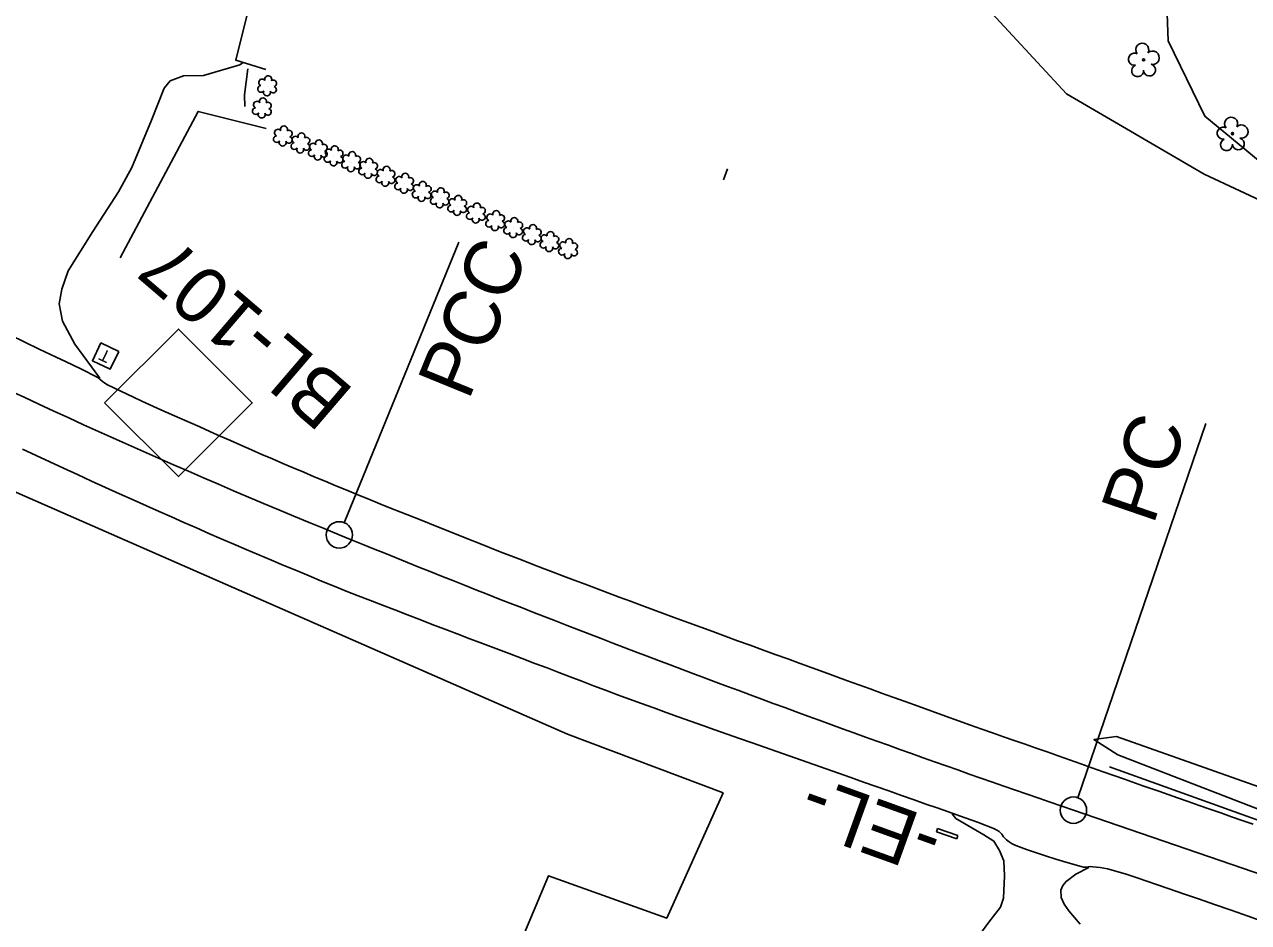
# Model space of a CAD drawing. Extents: x 478596 to 483012, y 490885 to 495165.
# Drawn here: x 479587.5 to 479935.6, y 493466.1 to 493721.5 of the extents above; entities that cross this region are included whole.
import ezdxf

# ---------------------------------------------------------------- set-up
doc = ezdxf.new("R2010")
doc.units = 0
for name, color, linetype in [('CTL Secondary Horizontal and Vertical CELL', 7, 'Continuous'), ('CTL Secondary Horizontal and Vertical Text', 7, 'Continuous'), ('Exist Guardrail', 7, 'Continuous'), ('Exist Horizontal Alignment', 7, 'Continuous'), ('Exist Horizontal Alignment Direction Label', 7, 'Continuous'), ('Exist Other Culture Area Outline', 7, 'Continuous'), ('Exist Other Culture Fence Line', 7, 'Continuous'), ('Exist Roads EOP', 7, 'Continuous'), ('Exist Roads Soil', 7, 'Continuous'), ('Exist Structure Minor Head and End Wall', 7, 'Continuous'), ('Exist Utilities Telephone Pedestal CELL', 7, 'Continuous'), ('Exist Vegetation Hedge Row', 7, 'Continuous'), ('Exist Vegetation Shrub CELL', 7, 'Continuous'), ('Exist Vegetation Tree CELL', 7, 'Continuous'), ('Exist Vegetation Woods Line', 7, 'Continuous')]:
    doc.layers.add(name, color=color, linetype=linetype)

msp = doc.modelspace()

# ---------------------------------------------------------------- linework, layer by layer
at = {"layer": 'CTL Secondary Horizontal and Vertical CELL'}
msp.add_line((479631.14, 493613.86), (479631.14, 493613.86), dxfattribs=at)
msp.add_lwpolyline([(479610.28, 493613.93), (479631.25, 493634.89), (479652.25, 493613.89), (479631.28, 493592.93)], close=True, dxfattribs=at)
at = {"layer": 'Exist Guardrail'}
msp.add_line((479896.1, 493510.36), (479982.05, 493479.53), dxfattribs=at)
at = {"layer": 'Exist Horizontal Alignment'}
for p, q in [((479678.44, 493579.83), (479710.98, 493659.56)), ((479887.04, 493501.61), (479923.5, 493608.01)), ((480512.88, 493283.24), (479885.83, 493498.07))]:
    msp.add_line(p, q, dxfattribs=at)
for centre in [(479677.03, 493576.36), (479885.83, 493498.07)]:
    msp.add_circle(centre, 3.75, dxfattribs=at)
for centre, radius, start, end in [((480448.9, 495467.9), 2042.96, 239.44048, 247.8014), ((481145.82, 497175.77), 3887.55, 247.8014, 251.08844)]:
    msp.add_arc(centre, radius, start, end, dxfattribs=at)
at = {"layer": 'Exist Other Culture Area Outline'}
for points in [[(479656.14, 493708.66), (479647.59, 493711.33), (479650.8, 493724.32), (479649.1, 493735.54)], [(479651.05, 493708.93), (479650.1, 493701.48), (479650.19, 493698.21)], [(479787.48, 493680.47), (479786.33, 493677.33)]]:
    msp.add_lwpolyline(points, dxfattribs=at)
at = {"layer": 'Exist Other Culture Fence Line'}
msp.add_lwpolyline([(479614.74, 493655.17), (479636.92, 493696.8), (479656.2, 493691.97)], dxfattribs=at)
at = {"layer": 'Exist Roads EOP'}
for points in [[(479936.94, 493494.07), (479933.81, 493495.16), (479930.76, 493496.22), (479927.73, 493497.28), (479924.66, 493498.35), (479921.57, 493499.43), (479918.43, 493500.53), (479915.41, 493501.59), (479910.12, 493503.44), (479905.6, 493505.03), (479900.35, 493506.87), (479897.36, 493507.92), (479894.24, 493509.02), (479891.09, 493510.13), (479887.91, 493511.25), (479884.71, 493512.38), (479881.5, 493513.51), (479878.33, 493514.63), (479875.19, 493515.73), (479872.09, 493516.81), (479869, 493517.89), (479865.91, 493518.97), (479862.83, 493520.05), (479859.74, 493521.13), (479856.53, 493522.26), (479853.1, 493523.48), (479849.45, 493524.79), (479845.56, 493526.2), (479841.66, 493527.61), (479837.97, 493528.94), (479834.49, 493530.2), (479831.2, 493531.39), (479828.01, 493532.54), (479824.79, 493533.71), (479821.55, 493534.9), (479818.27, 493536.1), (479814.95, 493537.32), (479811.56, 493538.56), (479808.09, 493539.82), (479804.55, 493541.1), (479800.98, 493542.39), (479797.42, 493543.68), (479793.86, 493544.98), (479790.32, 493546.27), (479786.79, 493547.56), (479783.3, 493548.84), (479779.84, 493550.1), (479776.41, 493551.35), (479773.02, 493552.59), (479769.67, 493553.82), (479766.36, 493555.04), (479763.1, 493556.26), (479759.85, 493557.47), (479756.62, 493558.68), (479753.38, 493559.9), (479750.15, 493561.11), (479746.96, 493562.32), (479743.84, 493563.5), (479740.79, 493564.66), (479737.81, 493565.79), (479734.85, 493566.92), (479731.88, 493568.06), (479728.87, 493569.22), (479725.85, 493570.4), (479722.81, 493571.58), (479719.78, 493572.78), (479716.75, 493573.97), (479713.73, 493575.18), (479710.77, 493576.36), (479705.24, 493578.56), (479700.1, 493580.6), (479694.56, 493582.81), (479691.59, 493584), (479688.54, 493585.23), (479685.45, 493586.47), (479682.34, 493587.74), (479679.2, 493589.03), (479676.06, 493590.32), (479672.97, 493591.61), (479669.92, 493592.88), (479666.92, 493594.15), (479663.94, 493595.42), (479660.96, 493596.69), (479657.99, 493597.98), (479655.01, 493599.26), (479652.04, 493600.56), (479649.07, 493601.86), (479646.11, 493603.16), (479643.14, 493604.47), (479640.21, 493605.77), (479637.33, 493607.05), (479634.5, 493608.3), (479631.72, 493609.52), (479626.27, 493611.96), (479620.9, 493614.43), (479618.46, 493615.57), (479614.9, 493617.24), (479610.91, 493619.17), (479610.25, 493619.56), (479609.69, 493619.98), (479608.92, 493620.67), (479608.34, 493621.09), (479603.52, 493623.59), (479599.19, 493625.65), (479596.54, 493626.87), (479591.69, 493629.16), (479587.74, 493631.08), (479583.11, 493633.38)], [(479940.28, 493466.24), (479935.53, 493467.9), (479930.68, 493469.59), (479925.9, 493471.25), (479921.38, 493472.83), (479917.11, 493474.32), (479913.09, 493475.72), (479909.49, 493476.97), (479903.98, 493478.85), (479900.52, 493479.97), (479895.53, 493481.4), (479893.39, 493481.8), (479891.39, 493482), (479890.65, 493482.02), (479890.1, 493481.98), (479889.74, 493481.88), (479889.34, 493481.83), (479888.66, 493481.9), (479883.68, 493483.25), (479880.79, 493484.16), (479877.88, 493485.12), (479872.52, 493486.93), (479869.49, 493488.05), (479868.43, 493488.54), (479867.55, 493489.06), (479866.79, 493489.64), (479866.18, 493490.23), (479865.95, 493490.52), (479865.43, 493491.28), (479865.25, 493491.48), (479865.08, 493491.65), (479864.66, 493491.98), (479864.08, 493492.36), (479863.33, 493492.77), (479858.54, 493494.68), (479855.01, 493495.94), (479850.02, 493497.69), (479847.06, 493498.72), (479843.89, 493499.82), (479840.53, 493501.01), (479836.96, 493502.26), (479833.31, 493503.55), (479829.69, 493504.82), (479826.1, 493506.08), (479822.56, 493507.32), (479819.03, 493508.55), (479815.51, 493509.79), (479811.99, 493511.03), (479808.49, 493512.27), (479804.98, 493513.51), (479801.47, 493514.75), (479797.95, 493515.98), (479794.42, 493517.21), (479790.89, 493518.44), (479787.37, 493519.67), (479783.87, 493520.91), (479780.39, 493522.16), (479776.91, 493523.4), (479773.43, 493524.65), (479769.95, 493525.89), (479766.47, 493527.14), (479763, 493528.38), (479759.55, 493529.64), (479756.12, 493530.91), (479752.71, 493532.18), (479749.33, 493533.46), (479745.99, 493534.72), (479742.7, 493535.98), (479739.44, 493537.23), (479736.13, 493538.51), (479732.67, 493539.83), (479729.06, 493541.19), (479725.31, 493542.61), (479721.52, 493544.04), (479717.8, 493545.45), (479714.15, 493546.84), (479710.57, 493548.21), (479707.03, 493549.56), (479703.48, 493550.92), (479699.93, 493552.29), (479696.38, 493553.65), (479692.84, 493555.02), (479689.34, 493556.37), (479685.87, 493557.72), (479682.44, 493559.05), (479679.01, 493560.4), (479675.53, 493561.79), (479672.01, 493563.23), (479668.45, 493564.7), (479664.87, 493566.2), (479661.29, 493567.7), (479657.71, 493569.2), (479654.14, 493570.71), (479650.57, 493572.22), (479647.02, 493573.74), (479643.47, 493575.27), (479639.94, 493576.8), (479636.4, 493578.35), (479632.86, 493579.89), (479629.31, 493581.45), (479625.76, 493583.01), (479622.15, 493584.61), (479618.41, 493586.28), (479614.55, 493588.02), (479610.58, 493589.82), (479606.56, 493591.66), (479602.57, 493593.49), (479598.62, 493595.32), (479594.7, 493597.14), (479590.8, 493598.96), (479586.93, 493600.76)]]:
    msp.add_lwpolyline(points, dxfattribs=at)
at = {"layer": 'Exist Roads Soil'}
for points in [[(479649.67, 493710.68), (479648.77, 493710.08), (479638.4, 493706.97), (479632.75, 493706.94), (479628.96, 493705.46), (479627.23, 493703.37), (479623.57, 493694.34), (479618.02, 493680.83), (479614.21, 493673.87), (479606.95, 493662.62), (479599.93, 493651.49), (479598.16, 493646.26), (479597.33, 493642.02), (479598.35, 493637.13), (479601.78, 493630.63), (479608.95, 493620.95)], [(479851.32, 493497.04), (479852.36, 493495.74), (479860.32, 493491.06), (479863.2, 493489.26), (479864.77, 493486.6), (479866.05, 493483.62), (479866.18, 493479.43), (479865.93, 493473.04), (479865.12, 493470.45), (479861.76, 493466.26), (479858.89, 493462.36)], [(479890.25, 493481.73), (479886.49, 493479.86), (479883.73, 493477.8), (479882.82, 493476.68), (479882.28, 493475.33), (479882.36, 493473.27), (479883.21, 493471.33), (479884.47, 493469.43), (479887.77, 493465.65)]]:
    msp.add_lwpolyline(points, dxfattribs=at)
at = {"layer": 'Exist Structure Minor Head and End Wall'}
for p, q in [((479846.84, 493491.93), (479847.17, 493492.88)), ((479847.17, 493492.88), (479852.97, 493490.86)), ((479846.84, 493491.93), (479852.64, 493489.92)), ((479852.64, 493489.92), (479852.97, 493490.86))]:
    msp.add_line(p, q, dxfattribs=at)
at = {"layer": 'Exist Utilities Telephone Pedestal CELL'}
msp.add_line((479610.6, 493627.16), (479610.6, 493627.16), dxfattribs=at)
msp.add_lwpolyline([(479614.28, 493628.54), (479609.23, 493630.95), (479606.82, 493625.9), (479611.87, 493623.49), (479614.28, 493628.54)], dxfattribs=at)
at = {"layer": 'Exist Vegetation Hedge Row'}
for points in [[(479912.31, 493729.75), (479912.77, 493716.89), (479923.17, 493695.39), (479948.15, 493674.84), (479943.28, 493669.47), (479923.02, 493678.95), (479883.84, 493701.77), (479859.15, 493728.66)], [(479982.85, 493482.21), (479949.94, 493493.89), (479898.42, 493513.77), (479891.65, 493518.15), (479898.04, 493519.04), (479985.49, 493488.15)]]:
    msp.add_lwpolyline(points, dxfattribs=at)
at = {"layer": 'Exist Vegetation Shrub CELL'}
for p, q in [((479656.58, 493703.89), (479656.58, 493703.89)), ((479655.09, 493697.58), (479655.09, 493697.58)), ((479661.06, 493689.62), (479661.06, 493689.62)), ((479666.04, 493687.62), (479666.04, 493687.62)), ((479671.01, 493685.63), (479671.01, 493685.63)), ((479675.49, 493683.97), (479675.49, 493683.97)), ((479680.47, 493682.32), (479680.47, 493682.32)), ((479685.33, 493680.43), (479685.33, 493680.43)), ((479690.25, 493678.17), (479690.25, 493678.17)), ((479695.56, 493676.18), (479695.56, 493676.18)), ((479700.54, 493673.85), (479700.54, 493673.85)), ((479705.68, 493672.03), (479705.68, 493672.03)), ((479710.65, 493669.87), (479710.65, 493669.87)), ((479715.96, 493667.71), (479715.96, 493667.71)), ((479721.43, 493665.56), (479721.43, 493665.56)), ((479726.57, 493663.57), (479726.57, 493663.57)), ((479731.88, 493661.57), (479731.88, 493661.57)), ((479736.86, 493659.58), (479736.86, 493659.58)), ((479742.16, 493657.59), (479742.16, 493657.59))]:
    msp.add_line(p, q, dxfattribs=at)
for centre, radius, start, end in [((479655.1, 493705.01), 0.968, 35.8908, 245.4216), ((479656.81, 493705.93), 0.99, 334.8391, 200.4717), ((479658.26, 493704.75), 0.929, 284.4567, 126.0861), ((479654.78, 493703.18), 0.955, 95.1099, 327.9534), ((479656.46, 493702.2), 0.984, 151.2797, 21.387), ((479658.22, 493702.96), 0.937, 204.9913, 73.4601), ((479653.61, 493698.71), 0.968, 35.8908, 245.4216), ((479655.32, 493699.62), 0.99, 334.8391, 200.4717), ((479656.76, 493698.45), 0.929, 284.4567, 126.0861), ((479653.29, 493696.88), 0.955, 95.1099, 327.9534), ((479654.96, 493695.9), 0.984, 151.2797, 21.387), ((479656.73, 493696.65), 0.937, 204.9913, 73.4601), ((479659.58, 493690.74), 0.968, 35.8908, 245.4216), ((479661.29, 493691.66), 0.99, 334.8391, 200.4717), ((479662.73, 493690.48), 0.929, 284.4567, 126.0861), ((479659.26, 493688.91), 0.955, 95.1099, 327.9534), ((479660.93, 493687.93), 0.984, 151.2797, 21.387), ((479662.7, 493688.69), 0.937, 204.9913, 73.4601), ((479664.24, 493686.92), 0.955, 95.1099, 327.9534), ((479664.56, 493688.75), 0.968, 35.8908, 245.4216), ((479666.27, 493689.67), 0.99, 334.8391, 200.4717), ((479667.71, 493688.49), 0.929, 284.4567, 126.0861), ((479671.24, 493687.67), 0.99, 334.8391, 200.4717), ((479665.91, 493685.94), 0.984, 151.2797, 21.387), ((479667.68, 493686.7), 0.937, 204.9913, 73.4601), ((479669.21, 493684.93), 0.955, 95.1099, 327.9534), ((479669.53, 493686.76), 0.968, 35.8908, 245.4216), ((479670.89, 493683.95), 0.984, 151.2797, 21.387), ((479672.65, 493684.7), 0.937, 204.9913, 73.4601), ((479672.69, 493686.5), 0.929, 284.4567, 126.0861), ((479674.01, 493685.1), 0.968, 35.8908, 245.4216), ((479675.72, 493686.01), 0.99, 334.8391, 200.4717), ((479677.16, 493684.84), 0.929, 284.4567, 126.0861), ((479678.98, 493683.44), 0.968, 35.8908, 245.4216), ((479680.7, 493684.36), 0.99, 334.8391, 200.4717), ((479673.69, 493683.27), 0.955, 95.1099, 327.9534), ((479675.36, 493682.29), 0.984, 151.2797, 21.387), ((479677.13, 493683.05), 0.937, 204.9913, 73.4601), ((479678.67, 493681.61), 0.955, 95.1099, 327.9534), ((479680.34, 493680.63), 0.984, 151.2797, 21.387), ((479682.1, 493681.39), 0.937, 204.9913, 73.4601), ((479682.14, 493683.18), 0.929, 284.4567, 126.0861), ((479683.85, 493681.56), 0.968, 35.8908, 245.4216), ((479685.56, 493682.47), 0.99, 334.8391, 200.4717), ((479687, 493681.3), 0.929, 284.4567, 126.0861), ((479690.48, 493680.21), 0.99, 334.8391, 200.4717), ((479683.53, 493679.73), 0.955, 95.1099, 327.9534), ((479685.2, 493678.75), 0.984, 151.2797, 21.387), ((479686.97, 493679.51), 0.937, 204.9913, 73.4601), ((479688.45, 493677.46), 0.955, 95.1099, 327.9534), ((479688.77, 493679.29), 0.968, 35.8908, 245.4216), ((479691.89, 493677.24), 0.937, 204.9913, 73.4601), ((479691.92, 493679.04), 0.929, 284.4567, 126.0861), ((479694.08, 493677.3), 0.968, 35.8908, 245.4216), ((479695.79, 493678.22), 0.99, 334.8391, 200.4717), ((479697.23, 493677.04), 0.929, 284.4567, 126.0861), ((479690.12, 493676.48), 0.984, 151.2797, 21.387), ((479693.76, 493675.47), 0.955, 95.1099, 327.9534), ((479695.43, 493674.49), 0.984, 151.2797, 21.387), ((479697.2, 493675.25), 0.937, 204.9913, 73.4601), ((479698.74, 493673.15), 0.955, 95.1099, 327.9534), ((479699.05, 493674.98), 0.968, 35.8908, 245.4216), ((479700.76, 493675.89), 0.99, 334.8391, 200.4717), ((479702.21, 493674.72), 0.929, 284.4567, 126.0861), ((479704.19, 493673.15), 0.968, 35.8908, 245.4216), ((479705.91, 493674.07), 0.99, 334.8391, 200.4717), ((479700.41, 493672.17), 0.984, 151.2797, 21.387), ((479702.17, 493672.92), 0.937, 204.9913, 73.4601), ((479703.88, 493671.32), 0.955, 95.1099, 327.9534), ((479705.55, 493670.34), 0.984, 151.2797, 21.387), ((479707.31, 493671.1), 0.937, 204.9913, 73.4601), ((479707.35, 493672.9), 0.929, 284.4567, 126.0861), ((479709.17, 493671), 0.968, 35.8908, 245.4216), ((479710.88, 493671.91), 0.99, 334.8391, 200.4717), ((479712.32, 493670.74), 0.929, 284.4567, 126.0861), ((479716.19, 493669.75), 0.99, 334.8391, 200.4717), ((479708.85, 493669.17), 0.955, 95.1099, 327.9534), ((479710.52, 493668.19), 0.984, 151.2797, 21.387), ((479712.29, 493668.94), 0.937, 204.9913, 73.4601), ((479714.16, 493667.01), 0.955, 95.1099, 327.9534), ((479714.48, 493668.84), 0.968, 35.8908, 245.4216), ((479717.6, 493666.78), 0.937, 204.9913, 73.4601), ((479717.63, 493668.58), 0.929, 284.4567, 126.0861), ((479719.95, 493666.68), 0.968, 35.8908, 245.4216), ((479721.66, 493667.6), 0.99, 334.8391, 200.4717), ((479723.1, 493666.43), 0.929, 284.4567, 126.0861), ((479715.83, 493666.03), 0.984, 151.2797, 21.387), ((479719.63, 493664.85), 0.955, 95.1099, 327.9534), ((479721.3, 493663.87), 0.984, 151.2797, 21.387), ((479723.07, 493664.63), 0.937, 204.9913, 73.4601), ((479724.77, 493662.86), 0.955, 95.1099, 327.9534), ((479725.09, 493664.69), 0.968, 35.8908, 245.4216), ((479726.8, 493665.61), 0.99, 334.8391, 200.4717), ((479728.21, 493662.64), 0.937, 204.9913, 73.4601), ((479728.25, 493664.43), 0.929, 284.4567, 126.0861), ((479730.4, 493662.7), 0.968, 35.8908, 245.4216), ((479732.11, 493663.61), 0.99, 334.8391, 200.4717), ((479726.45, 493661.88), 0.984, 151.2797, 21.387), ((479730.08, 493660.87), 0.955, 95.1099, 327.9534), ((479731.75, 493659.89), 0.984, 151.2797, 21.387), ((479733.52, 493660.65), 0.937, 204.9913, 73.4601), ((479733.55, 493662.44), 0.929, 284.4567, 126.0861), ((479735.37, 493660.71), 0.968, 35.8908, 245.4216), ((479737.09, 493661.62), 0.99, 334.8391, 200.4717), ((479738.53, 493660.45), 0.929, 284.4567, 126.0861), ((479742.39, 493659.63), 0.99, 334.8391, 200.4717), ((479735.06, 493658.88), 0.955, 95.1099, 327.9534), ((479736.73, 493657.9), 0.984, 151.2797, 21.387), ((479738.49, 493658.65), 0.937, 204.9913, 73.4601), ((479740.36, 493656.89), 0.955, 95.1099, 327.9534), ((479740.68, 493658.72), 0.968, 35.8908, 245.4216), ((479743.8, 493656.66), 0.937, 204.9913, 73.4601), ((479743.84, 493658.46), 0.929, 284.4567, 126.0861), ((479742.04, 493655.91), 0.984, 151.2797, 21.387)]:
    msp.add_arc(centre, radius, start, end, dxfattribs=at)
at = {"layer": 'Exist Vegetation Tree CELL'}
for p, q in [((479905.78, 493711.46), (479905.78, 493711.46)), ((479931.06, 493690.44), (479931.06, 493690.44))]:
    msp.add_line(p, q, dxfattribs=at)
for centre in [(479905.78, 493711.46), (479931.06, 493690.44)]:
    msp.add_circle(centre, 0.326, dxfattribs=at)
for centre, radius, start, end in [((479905.4, 493714.33), 1.86, 330.1651, 219.7134), ((479903.18, 493711.61), 1.73, 62.6636, 279.3457), ((479908.33, 493712.05), 1.9, 257.1011, 134.1999), ((479904.08, 493708.34), 1.69, 111.5671, 6.231), ((479907.46, 493708.56), 1.7, 181.2822, 74.56), ((479930.68, 493693.31), 1.86, 330.1651, 219.7134), ((479928.46, 493690.59), 1.73, 62.6636, 279.3457), ((479933.61, 493691.03), 1.9, 257.1011, 134.1999), ((479929.36, 493687.32), 1.69, 111.5671, 6.231), ((479932.74, 493687.54), 1.7, 181.2822, 74.56)]:
    msp.add_arc(centre, radius, start, end, dxfattribs=at)
at = {"layer": 'Exist Vegetation Woods Line'}
msp.add_lwpolyline([(479483.46, 493634.2), (479561.97, 493598.57), (479741.91, 493519.68), (479786.17, 493502.96), (479770.18, 493467.35), (479736.49, 493479.43), (479725.73, 493453.7), (479755.91, 493427.15), (479747.5, 493411.63), (479741.52, 493386.24), (479749.84, 493380.92), (479748.16, 493352.86), (479746.69, 493346.26)], dxfattribs=at)

# ---------------------------------------------------------------- texts
at = {"layer": 'CTL Secondary Horizontal and Vertical Text'}
msp.add_text('BL-107', height=16, rotation=139.3796, dxfattribs=at).set_placement((479681.69, 493617.32))
at = {"layer": 'Exist Horizontal Alignment'}
for s, rotation, p in [('PCC', 67.8014, (479713.77, 493614.3)), ('PC', 71.0884, (479908.52, 493578.89))]:
    msp.add_text(s, height=16, rotation=rotation, dxfattribs=at).set_placement(p)
at = {"layer": 'Exist Horizontal Alignment Direction Label'}
msp.add_text('-EL-', height=16, rotation=160.1765, dxfattribs=at).set_placement((479849.65, 493494.42))
at = {"layer": 'Exist Utilities Telephone Pedestal CELL'}
msp.add_text('T', height=3.42, rotation=154.4461, dxfattribs=at).set_placement((479612.36, 493628.22))

doc.saveas('drawing.dxf')
